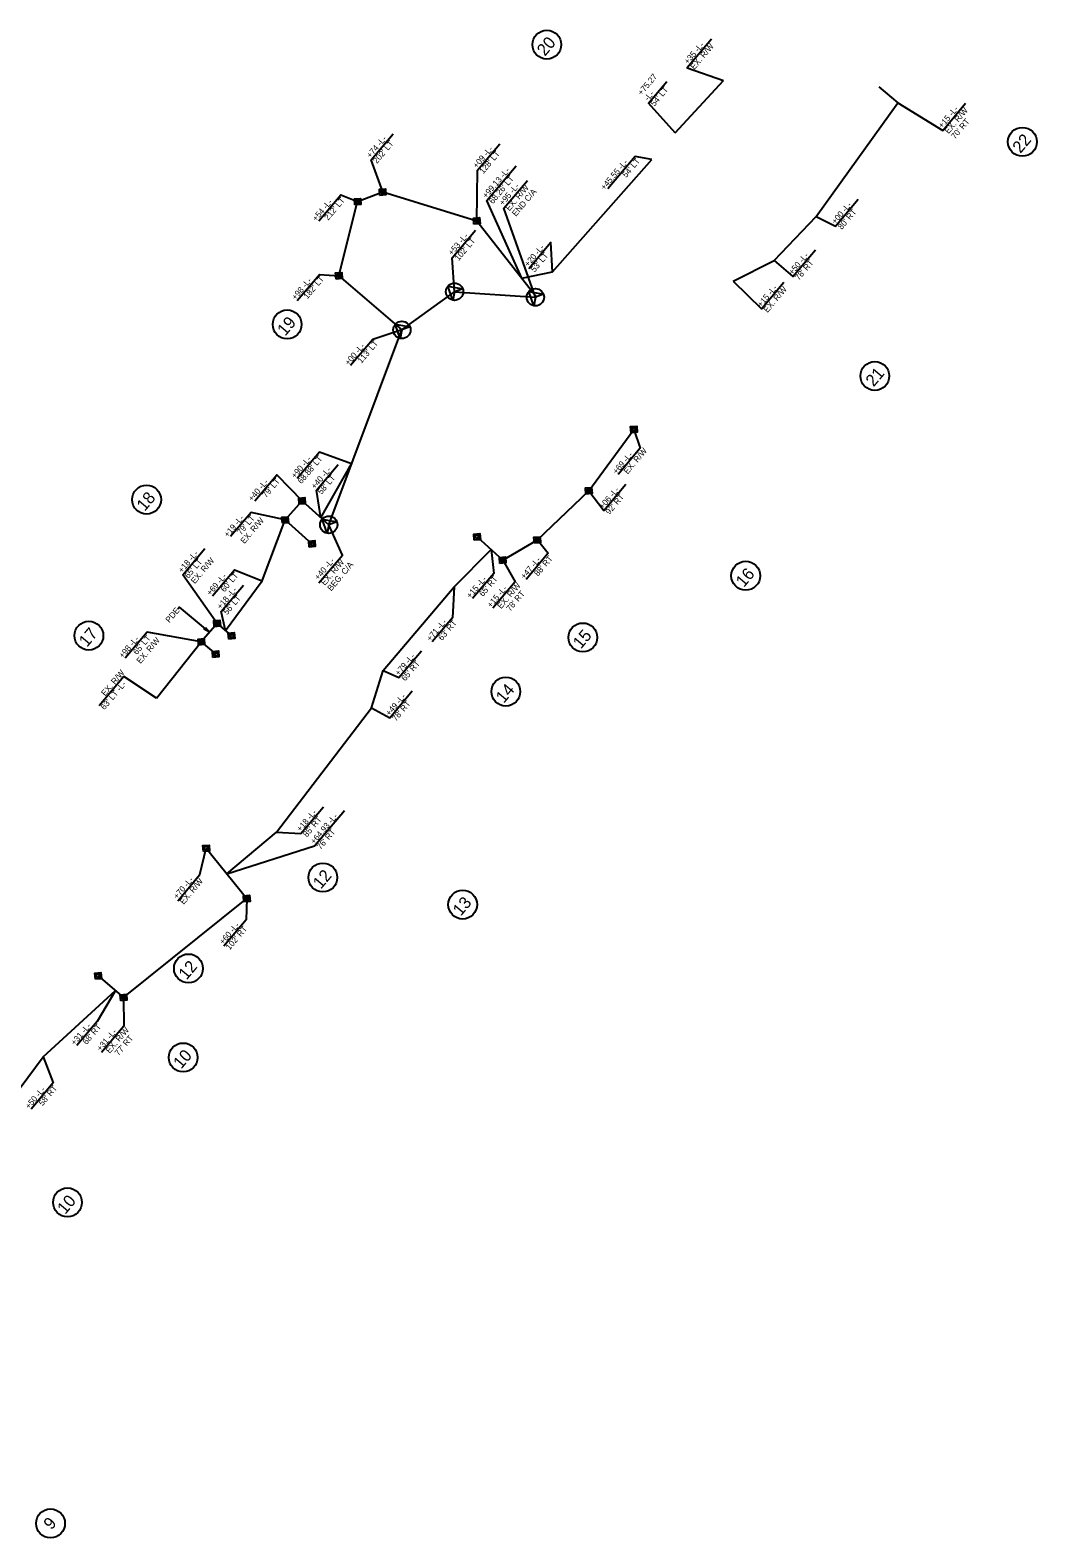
# Model space of a CAD drawing. Extents: x 1761749 to 1764136, y 422439 to 425054.
# Drawn here: x 1763299 to 1764136, y 423800 to 425054 of the extents above; entities that cross this region are included whole.
import ezdxf

# ---------------------------------------------------------------- set-up
doc = ezdxf.new("R2010")
doc.units = 0
for name, color, linetype in [('Prop Easement Construction', 7, 'Continuous'), ('Prop Easement Construction Station Offsets', 7, 'Continuous'), ('Prop Easement Permanent Drainage', 7, 'Continuous'), ('Prop Easement Permanent Drainage Station Offsets', 7, 'Continuous'), ('Prop Easement Permanent Utility', 7, 'Continuous'), ('Prop Easement Permanent Utility Station Offsets', 7, 'Continuous'), ('Prop Parcel Number CELL', 7, 'Continuous'), ('Prop Parcel Number Text', 7, 'Continuous'), ('Prop ROW Marker CA CELL', 7, 'Continuous'), ('Prop ROW Permanent Easement CELL', 7, 'Continuous'), ('Prop ROW RW CA Lines', 7, 'Continuous'), ('Prop ROW Station Offsets', 7, 'Continuous')]:
    doc.layers.add(name, color=color, linetype=linetype)

msp = doc.modelspace()

# ---------------------------------------------------------------- linework, layer by layer
at = {"layer": 'Prop Easement Construction'}
for p, q in [((1763835.4, 424968.3), (1763875.5, 425012)), ((1764004.7, 425006.7), (1764020.5, 424993.2)), ((1763952.6, 424898.8), (1764020.5, 424993.2)), ((1763733.3, 424852.7), (1763815.9, 424946.1)), ((1763917.7, 424862.1), (1763952.6, 424898.8)), ((1763883.7, 424845.1), (1763917.7, 424862.1)), ((1763707.9, 424847.6), (1763733.3, 424852.7)), ((1763540.8, 424648.4), (1763566.3, 424693.2)), ((1763592.6, 424521.2), (1763651.6, 424590.8)), ((1763404, 424498.3), (1763441.3, 424545.2)), ((1763582.8, 424490.3), (1763592.6, 424521.2)), ((1763503.7, 424387), (1763582.8, 424490.3)), ((1763462.5, 424352.3), (1763503.7, 424387)), ((1763309.8, 424200), (1763369.8, 424255.3)), ((1763209.4, 424065.9), (1763309.8, 424200))]:
    msp.add_line(p, q, dxfattribs=at)
for points in [[(1763461.3, 424554.6), (1763491.9, 424596), (1763511, 424646.5)], [(1763651.6, 424590.8), (1763682.4, 424621.9)]]:
    msp.add_lwpolyline(points, dxfattribs=at)
at = {"layer": 'Prop Easement Construction Station Offsets'}
for points in [[(1763865.5, 425046.2), (1763845.3, 425022.3), (1763875.5, 425012)], [(1763835.4, 424968.3), (1763813.3, 424993.1), (1763828.4, 425011)], [(1764020.5, 424993.2), (1764058, 424970.4), (1764077, 424992.9)], [(1763815.9, 424946.1), (1763802.1, 424948.6), (1763779.4, 424921.8)], [(1763707.9, 424847.6), (1763678.8, 424912.2), (1763703.1, 424940.9)], [(1763952.6, 424898.8), (1763968.9, 424890.9), (1763987.7, 424913.1)], [(1763733.3, 424852.7), (1763732, 424877.1), (1763713.6, 424855.3)], [(1763917.7, 424862.1), (1763933.2, 424848.8), (1763952, 424871)], [(1763883.7, 424845.1), (1763907.1, 424822), (1763925.8, 424844.1)], [(1763566.3, 424693.2), (1763539.5, 424702.8), (1763521, 424681)], [(1763540.8, 424648.4), (1763537.1, 424671.4), (1763555.1, 424692.7)], [(1763682.4, 424621.9), (1763684.5, 424601.9), (1763666.9, 424581.2)], [(1763450.6, 424583.4), (1763469, 424605.1), (1763491.9, 424596)], [(1763461.3, 424554.6), (1763457.9, 424570.5), (1763476.3, 424592.3)], [(1763651.6, 424590.8), (1763650.2, 424565.2), (1763633.2, 424545.2)], [(1763592.6, 424521.2), (1763605.7, 424515.5), (1763624.5, 424537.7)], [(1763404, 424498.3), (1763377, 424516.3), (1763356.4, 424492)], [(1763582.8, 424490.3), (1763598.1, 424482.1), (1763616.8, 424504.3)], [(1763503.7, 424387), (1763524, 424385.9), (1763542.8, 424408)], [(1763462.5, 424352.3), (1763535.5, 424375.5), (1763560.5, 424405)], [(1763369.8, 424255.3), (1763354.7, 424229.4), (1763337.9, 424209.6)], [(1763309.8, 424200), (1763318.2, 424178.4), (1763299.8, 424156.6)]]:
    msp.add_lwpolyline(points, dxfattribs=at)
at = {"layer": 'Prop Easement Permanent Drainage'}
for p, q in [((1763555.7, 424849.6), (1763571.3, 424911.2)), ((1763571.3, 424911.2), (1763592.2, 424919.2)), ((1763592.2, 424919.2), (1763670.4, 424895.2)), ((1763670.4, 424895.2), (1763719.9, 424832.4)), ((1763555.7, 424849.6), (1763608.1, 424804.5)), ((1763763.5, 424670.8), (1763801.1, 424721.8)), ((1763720.8, 424629.9), (1763763.5, 424670.8)), ((1763670.7, 424632.5), (1763692, 424613.1)), ((1763692, 424613.1), (1763720.8, 424629.9)), ((1763454.5, 424560.5), (1763441.3, 424545.2)), ((1763454.5, 424560.5), (1763466.4, 424550.2)), ((1763441.3, 424545.2), (1763453.3, 424534.9)), ((1763445.3, 424373.5), (1763479.2, 424331.7)), ((1763376.7, 424249.5), (1763479.2, 424331.7)), ((1763355.5, 424267.4), (1763376.7, 424249.5))]:
    msp.add_line(p, q, dxfattribs=at)
at = {"layer": 'Prop Easement Permanent Drainage Station Offsets'}
for points in [[(1763592.2, 424919.2), (1763582.6, 424945.9), (1763601, 424967.6)], [(1763670.4, 424895.2), (1763671, 424937.4), (1763689.5, 424959.1)], [(1763539, 424895.1), (1763557.4, 424916.9), (1763571.3, 424911.2)], [(1763521.1, 424829), (1763539.5, 424850.7), (1763555.7, 424849.6)], [(1763801.1, 424721.8), (1763806.4, 424706.1), (1763788, 424684.3)], [(1763763.5, 424670.8), (1763776, 424654.4), (1763794.5, 424676.2)], [(1763454.5, 424560.5), (1763425.8, 424600.9), (1763444.3, 424622.7)], [(1763720.8, 424629.9), (1763729.9, 424618.8), (1763711.4, 424597)], [(1763692, 424613.1), (1763702.4, 424595), (1763683.9, 424573.2)], [(1763448.1, 424553.1), (1763423.2, 424573.9), (1763421.8, 424572.2)], [(1763441.3, 424545.2), (1763396.4, 424553.3), (1763378.1, 424531.6)], [(1763421.7, 424329.9), (1763440.2, 424351.6), (1763445.3, 424373.5)], [(1763479.2, 424331.7), (1763478.5, 424313.9), (1763460, 424292.1)], [(1763376.7, 424249.5), (1763376.8, 424225.5), (1763358.3, 424203.7)]]:
    msp.add_lwpolyline(points, dxfattribs=at)
msp.add_lwpolyline([(1763444.7, 424557), (1763448.1, 424553.1), (1763443.6, 424555.7), (1763444.7, 424556)], close=True, dxfattribs=at)
at = {"layer": 'Prop Easement Permanent Utility'}
for q in [(1763525.1, 424662.3), (1763533.3, 424626.7)]:
    msp.add_line((1763511, 424646.5), q, dxfattribs=at)
msp.add_lwpolyline([(1763525.1, 424662.3), (1763547.3, 424642.5)], dxfattribs=at)
at = {"layer": 'Prop Easement Permanent Utility Station Offsets'}
for points in [[(1763485.8, 424662.3), (1763504.2, 424684), (1763525.1, 424662.3)], [(1763511, 424646.5), (1763482.7, 424652.8), (1763465.7, 424632.8)]]:
    msp.add_lwpolyline(points, dxfattribs=at)
at = {"layer": 'Prop Parcel Number CELL'}
for p, q in [((1763728.7, 425041.7), (1763728.7, 425041.7)), ((1764124.2, 424960.9), (1764124.2, 424960.9)), ((1763512.7, 424809.1), (1763512.7, 424809.1)), ((1764001.5, 424766.2), (1764001.5, 424766.2)), ((1763395.8, 424663.4), (1763395.8, 424663.4)), ((1763894.1, 424600.1), (1763894.1, 424600.1)), ((1763347.8, 424550.3), (1763347.8, 424550.3)), ((1763758.6, 424548.8), (1763758.6, 424548.8)), ((1763694.6, 424503.8), (1763694.6, 424503.8)), ((1763542.4, 424349.2), (1763542.4, 424349.2)), ((1763658.7, 424326.7), (1763658.7, 424326.7)), ((1763430.6, 424273.6), (1763430.6, 424273.6)), ((1763426.2, 424199.6), (1763426.2, 424199.6)), ((1763330, 424079.1), (1763330, 424079.1)), ((1763315.9, 423812.2), (1763315.9, 423812.2))]:
    msp.add_line(p, q, dxfattribs=at)
for centre in [(1763728.7, 425041.7), (1764124.2, 424960.9), (1763512.7, 424809.1), (1764001.5, 424766.2), (1763395.8, 424663.4), (1763894.1, 424600.1), (1763347.8, 424550.3), (1763758.6, 424548.8), (1763694.6, 424503.8), (1763542.4, 424349.2), (1763658.7, 424326.7), (1763430.6, 424273.6), (1763426.2, 424199.6), (1763330, 424079.1), (1763315.9, 423812.2)]:
    msp.add_circle(centre, 12, dxfattribs=at)
at = {"layer": 'Prop ROW Marker CA CELL'}
for p, q in [((1763717.9, 424824.6), (1763713.7, 424836.4)), ((1763713.7, 424836.4), (1763726, 424834.1)), ((1763726, 424834.1), (1763719.2, 424831.7)), ((1763719.2, 424831.7), (1763717.9, 424824.6)), ((1763606.8, 424797.4), (1763602.6, 424809.2)), ((1763602.6, 424809.2), (1763614.8, 424807)), ((1763614.8, 424807), (1763608.1, 424804.5)), ((1763608.1, 424804.5), (1763606.8, 424797.4)), ((1763546, 424635.4), (1763541.8, 424647.2)), ((1763541.8, 424647.2), (1763554.1, 424645)), ((1763554.1, 424645), (1763547.3, 424642.5)), ((1763547.3, 424642.5), (1763546, 424635.4))]:
    msp.add_line(p, q, dxfattribs=at)
for centre in [(1763719.2, 424831.7), (1763608.1, 424804.5), (1763547.3, 424642.5)]:
    msp.add_circle(centre, 7.2, dxfattribs=at)
at = {"layer": 'Prop ROW Permanent Easement CELL'}
for p, q in [((1763571.3, 424911.2), (1763571.3, 424911.2)), ((1763592.2, 424919.2), (1763592.2, 424919.2)), ((1763670.4, 424895.2), (1763670.4, 424895.2)), ((1763555.7, 424849.6), (1763555.7, 424849.6)), ((1763801.1, 424721.8), (1763801.1, 424721.8)), ((1763763.5, 424670.8), (1763763.5, 424670.8)), ((1763525.1, 424662.3), (1763525.1, 424662.3)), ((1763511, 424646.5), (1763511, 424646.5)), ((1763670.7, 424632.5), (1763670.7, 424632.5)), ((1763533.3, 424626.7), (1763533.3, 424626.7)), ((1763720.8, 424629.9), (1763720.8, 424629.9)), ((1763692, 424613.1), (1763692, 424613.1)), ((1763454.5, 424560.5), (1763454.5, 424560.5)), ((1763441.3, 424545.2), (1763441.3, 424545.2)), ((1763466.4, 424550.2), (1763466.4, 424550.2)), ((1763453.3, 424534.9), (1763453.3, 424534.9)), ((1763445.3, 424373.5), (1763445.3, 424373.5)), ((1763479.2, 424331.7), (1763479.2, 424331.7)), ((1763355.5, 424267.4), (1763355.5, 424267.4)), ((1763376.7, 424249.5), (1763376.7, 424249.5))]:
    msp.add_line(p, q, dxfattribs=at)
for points in [[(1763589.9, 424916.4), (1763589.4, 424921.5), (1763594.5, 424921.9), (1763594.9, 424916.9)], [(1763591, 424917.8), (1763590.8, 424920.3), (1763593.4, 424920.6), (1763593.6, 424918)], [(1763569, 424908.4), (1763568.6, 424913.5), (1763573.7, 424913.9), (1763574.1, 424908.8)], [(1763570.2, 424909.8), (1763570, 424912.3), (1763572.5, 424912.5), (1763572.7, 424910)], [(1763668.1, 424892.4), (1763667.7, 424897.5), (1763672.8, 424897.9), (1763673.2, 424892.8)], [(1763669.3, 424893.8), (1763669.1, 424896.3), (1763671.6, 424896.5), (1763671.8, 424894)], [(1763553.4, 424846.8), (1763553, 424851.9), (1763558.1, 424852.3), (1763558.5, 424847.2)], [(1763554.6, 424848.2), (1763554.4, 424850.7), (1763556.9, 424850.9), (1763557.1, 424848.4)], [(1763798.7, 424719), (1763798.3, 424724.1), (1763803.4, 424724.5), (1763803.8, 424719.5)], [(1763799.9, 424720.4), (1763799.7, 424723), (1763802.2, 424723.2), (1763802.4, 424720.6)], [(1763761.2, 424668), (1763760.8, 424673.1), (1763765.8, 424673.5), (1763766.3, 424668.4)], [(1763762.4, 424669.4), (1763762.1, 424671.9), (1763764.7, 424672.1), (1763764.9, 424669.6)], [(1763522.8, 424659.6), (1763522.3, 424664.7), (1763527.4, 424665.1), (1763527.8, 424660)], [(1763523.9, 424661), (1763523.7, 424663.5), (1763526.3, 424663.7), (1763526.5, 424661.2)], [(1763508.7, 424643.7), (1763508.3, 424648.8), (1763513.3, 424649.2), (1763513.7, 424644.1)], [(1763509.8, 424645.1), (1763509.6, 424647.6), (1763512.2, 424647.8), (1763512.4, 424645.3)], [(1763668.3, 424629.7), (1763667.9, 424634.8), (1763673, 424635.2), (1763673.4, 424630.1)], [(1763669.5, 424631.1), (1763669.3, 424633.6), (1763671.8, 424633.8), (1763672, 424631.3)], [(1763718.5, 424627.1), (1763718, 424632.2), (1763723.1, 424632.6), (1763723.5, 424627.6)], [(1763531, 424624), (1763530.6, 424629), (1763535.6, 424629.5), (1763536, 424624.4)], [(1763532.1, 424625.3), (1763531.9, 424627.9), (1763534.5, 424628.1), (1763534.7, 424625.6)], [(1763719.6, 424628.5), (1763719.4, 424631.1), (1763722, 424631.3), (1763722.2, 424628.7)], [(1763689.7, 424610.4), (1763689.2, 424615.4), (1763694.3, 424615.9), (1763694.7, 424610.8)], [(1763690.8, 424611.7), (1763690.6, 424614.3), (1763693.1, 424614.5), (1763693.4, 424612)], [(1763452.1, 424557.7), (1763451.7, 424562.8), (1763456.8, 424563.2), (1763457.2, 424558.2)], [(1763453.3, 424559.1), (1763453.1, 424561.7), (1763455.6, 424561.9), (1763455.8, 424559.3)], [(1763439, 424542.5), (1763438.6, 424547.5), (1763443.6, 424547.9), (1763444, 424542.9)], [(1763440.1, 424543.8), (1763439.9, 424546.4), (1763442.5, 424546.6), (1763442.7, 424544)], [(1763464.1, 424547.4), (1763463.7, 424552.5), (1763468.7, 424552.9), (1763469.2, 424547.9)], [(1763465.2, 424548.8), (1763465, 424551.3), (1763467.6, 424551.6), (1763467.8, 424549)], [(1763451, 424532.2), (1763450.5, 424537.2), (1763455.6, 424537.7), (1763456, 424532.6)], [(1763452.1, 424533.5), (1763451.9, 424536.1), (1763454.5, 424536.3), (1763454.7, 424533.8)], [(1763443, 424370.8), (1763442.6, 424375.8), (1763447.7, 424376.2), (1763448.1, 424371.2)], [(1763444.2, 424372.1), (1763444, 424374.7), (1763446.5, 424374.9), (1763446.7, 424372.3)], [(1763476.8, 424329), (1763476.4, 424334.1), (1763481.5, 424334.5), (1763481.9, 424329.4)], [(1763478, 424330.4), (1763477.8, 424332.9), (1763480.3, 424333.1), (1763480.5, 424330.6)], [(1763353.2, 424264.7), (1763352.7, 424269.8), (1763357.8, 424270.2), (1763358.2, 424265.1)], [(1763354.3, 424266.1), (1763354.1, 424268.6), (1763356.7, 424268.8), (1763356.9, 424266.3)], [(1763374.4, 424246.7), (1763373.9, 424251.8), (1763379, 424252.2), (1763379.4, 424247.2)], [(1763375.5, 424248.1), (1763375.3, 424250.6), (1763377.9, 424250.9), (1763378.1, 424248.3)]]:
    msp.add_lwpolyline(points, close=True, dxfattribs=at)
at = {"layer": 'Prop ROW RW CA Lines'}
for p, q in [((1763608.1, 424804.5), (1763651.9, 424836.3)), ((1763650.6, 424829.2), (1763646.4, 424840.9)), ((1763646.4, 424840.9), (1763658.7, 424838.7)), ((1763651.9, 424836.3), (1763650.6, 424829.2)), ((1763658.7, 424838.7), (1763651.9, 424836.3)), ((1763651.9, 424836.3), (1763719.2, 424831.7)), ((1763547.3, 424642.5), (1763608.1, 424804.5))]:
    msp.add_line(p, q, dxfattribs=at)
msp.add_circle((1763651.9, 424836.3), 7.2, dxfattribs=at)
at = {"layer": 'Prop ROW Station Offsets'}
for points in [[(1763719.2, 424831.7), (1763692.9, 424905.6), (1763712.5, 424928.8)], [(1763651.9, 424836.3), (1763649.9, 424864.4), (1763669.4, 424887.4)], [(1763608.1, 424804.5), (1763584, 424796.5), (1763565.5, 424774.8)], [(1763539.1, 424594.1), (1763558.6, 424617.1), (1763547.3, 424642.5)]]:
    msp.add_lwpolyline(points, dxfattribs=at)

# ---------------------------------------------------------------- texts
at = {"layer": 'Prop Easement Construction Station Offsets'}
for s, p in [('+35 -L-', (1763846.1, 425025)), ('EX. R/W', (1763851.4, 425020.5)), ('+75.27', (1763807.5, 424999.1)), ('-L-', (1763812.9, 424994.5)), ("54' LT", (1763818.2, 424990)), ('+15 -L-', (1764057.5, 424971.8)), ('EX. R/W', (1764062.8, 424967.2)), ("70' RT", (1764068.2, 424962.7)), ('+45.55 -L-', (1763776.6, 424920.3)), ("54' LT", (1763794.7, 424930.7)), ('+99.13 -L-', (1763678.4, 424913.5)), ("68.26' LT", (1763683.8, 424908.9)), ('+00 -L-', (1763968.7, 424892)), ("80' RT", (1763974, 424887.5)), ('+20 -L-', (1763713.2, 424856.6)), ("53' LT", (1763718.5, 424852.1)), ('+50 -L-', (1763933, 424849.9)), ("78' RT", (1763938.3, 424845.3)), ('+15 -L-', (1763906.9, 424823)), ('EX. R/W', (1763912.2, 424818.5)), ('+90 -L-', (1763519.3, 424680.7)), ("68.88' LT", (1763524.6, 424676.1)), ('+40 -L-', (1763535.9, 424671.8)), ("58' LT", (1763541.3, 424667.3)), ('+69 -L-', (1763448.9, 424583.2)), ("60' LT", (1763460.6, 424586.1)), ('+15 -L-', (1763665.1, 424580.9)), ("65' RT", (1763675.6, 424582.4)), ('+18 -L-', (1763457.5, 424571.8)), ("56' LT", (1763462.8, 424567.2)), ('+71 -L-', (1763631.9, 424545.2)), ("63' RT", (1763641.6, 424545.8)), ('+79 -L-', (1763605.6, 424516.6)), ('EX. R/W', (1763361.3, 424499.7)), ("65' RT", (1763610.9, 424512.1)), ("63' LT -L-", (1763360.8, 424488.2)), ('+49 -L-', (1763597.9, 424483.2)), ("78' RT", (1763603.2, 424478.7)), ('+18 -L-', (1763523.8, 424386.9)), ("85' RT", (1763529.2, 424382.4)), ('+64.93 -L-', (1763535.3, 424376.5)), ("76' RT", (1763540.6, 424372)), ('+31 -L-', (1763336.1, 424209.3)), ("68' RT", (1763345.9, 424209.9)), ('+50 -L-', (1763298.1, 424156.4)), ("58' RT", (1763309.3, 424158.9))]:
    msp.add_text(s, height=5, rotation=49.7301, dxfattribs=at).set_placement(p)
at = {"layer": 'Prop Easement Permanent Drainage Station Offsets'}
for s, p in [('+74 -L-', (1763582, 424947)), ("202' LT", (1763587.4, 424942.4)), ('+09 -L-', (1763670.5, 424938.5)), ("128' LT", (1763675.8, 424933.9)), ('+54 -L-', (1763536.9, 424894.4)), ("212' LT", (1763546.8, 424895.2)), ('+98 -L-', (1763519.7, 424829)), ("182' LT", (1763529.5, 424829.8)), ('EX. R/W', (1763795.9, 424684.2)), ('+69 -L-', (1763786.7, 424684.2)), ('+06 -L-', (1763775.4, 424655.1)), ("92' RT", (1763780.7, 424650.6)), ('+18 -L-', (1763425.3, 424602.1)), ("65' LT", (1763430.6, 424597.5)), ('EX. R/W', (1763435.9, 424593)), ('+47 -L-', (1763710.1, 424596.9)), ("88' RT", (1763721.4, 424599.3)), ('EX. R/W', (1763690.7, 424572.2)), ('+15 -L-', (1763682.3, 424573.1)), ("78' RT", (1763698.2, 424570.1)), ('PDE', (1763414.8, 424560.6)), ('+98 -L-', (1763376.1, 424531.1)), ("65' LT", (1763387.8, 424534)), ('EX. R/W', (1763390.7, 424526.6)), ('+70 -L-', (1763421.3, 424330.9)), ('EX. R/W', (1763426.6, 424326.4)), ('+60 -L-', (1763459.6, 424293.1)), ("102' RT", (1763464.9, 424288.6)), ('+31 -L-', (1763357.5, 424204.5)), ('EX. R/W', (1763365.1, 424202.6)), ("77' RT", (1763372.5, 424200.6))]:
    msp.add_text(s, height=5, rotation=49.7301, dxfattribs=at).set_placement(p)
at = {"layer": 'Prop Easement Permanent Utility Station Offsets'}
for s, p in [("79' LT", (1763495.2, 424664.5)), ('+40 -L-', (1763483.6, 424661.6)), ('+19 -L-', (1763463.4, 424631.7)), ("79' LT", (1763474.3, 424633.7)), ('EX. R/W', (1763477.2, 424626.3))]:
    msp.add_text(s, height=5, rotation=49.7301, dxfattribs=at).set_placement(p)
at = {"layer": 'Prop Parcel Number Text'}
for s, p in [('20', (1763727.1, 425031.6)), ('22', (1764122.6, 424950.8)), ('19', (1763511.1, 424798.9)), ('21', (1764000.5, 424756.7)), ('18', (1763394.2, 424653.2)), ('16', (1763892.5, 424589.9)), ('17', (1763346.2, 424540.2)), ('15', (1763757, 424538.7)), ('14', (1763692.9, 424493.6)), ('12', (1763540.8, 424339.1)), ('13', (1763657.1, 424316.6)), ('12', (1763429, 424263.5)), ('10', (1763424.6, 424189.5)), ('10', (1763328.1, 424068.6)), ('9', (1763316.7, 423806.3))]:
    msp.add_text(s, height=10, rotation=49.7301, dxfattribs=at).set_placement(p)
at = {"layer": 'Prop ROW Station Offsets'}
for s, p in [('+95 -L-', (1763692.3, 424907.5)), ('EX. R/W', (1763697.6, 424903)), ('END C/A', (1763703, 424898.5)), ('+53 -L-', (1763649.9, 424866.1)), ("102' LT", (1763655.3, 424861.6)), ("113' LT", (1763574.5, 424776.3)), ('+00 -L-', (1763563.9, 424774.6)), ('+40 -L-', (1763538.7, 424596.1)), ('EX. R/W', (1763544, 424591.6)), ('BEG. C/A', (1763549.4, 424587))]:
    msp.add_text(s, height=5, rotation=49.7301, dxfattribs=at).set_placement(p)

doc.saveas('drawing.dxf')
